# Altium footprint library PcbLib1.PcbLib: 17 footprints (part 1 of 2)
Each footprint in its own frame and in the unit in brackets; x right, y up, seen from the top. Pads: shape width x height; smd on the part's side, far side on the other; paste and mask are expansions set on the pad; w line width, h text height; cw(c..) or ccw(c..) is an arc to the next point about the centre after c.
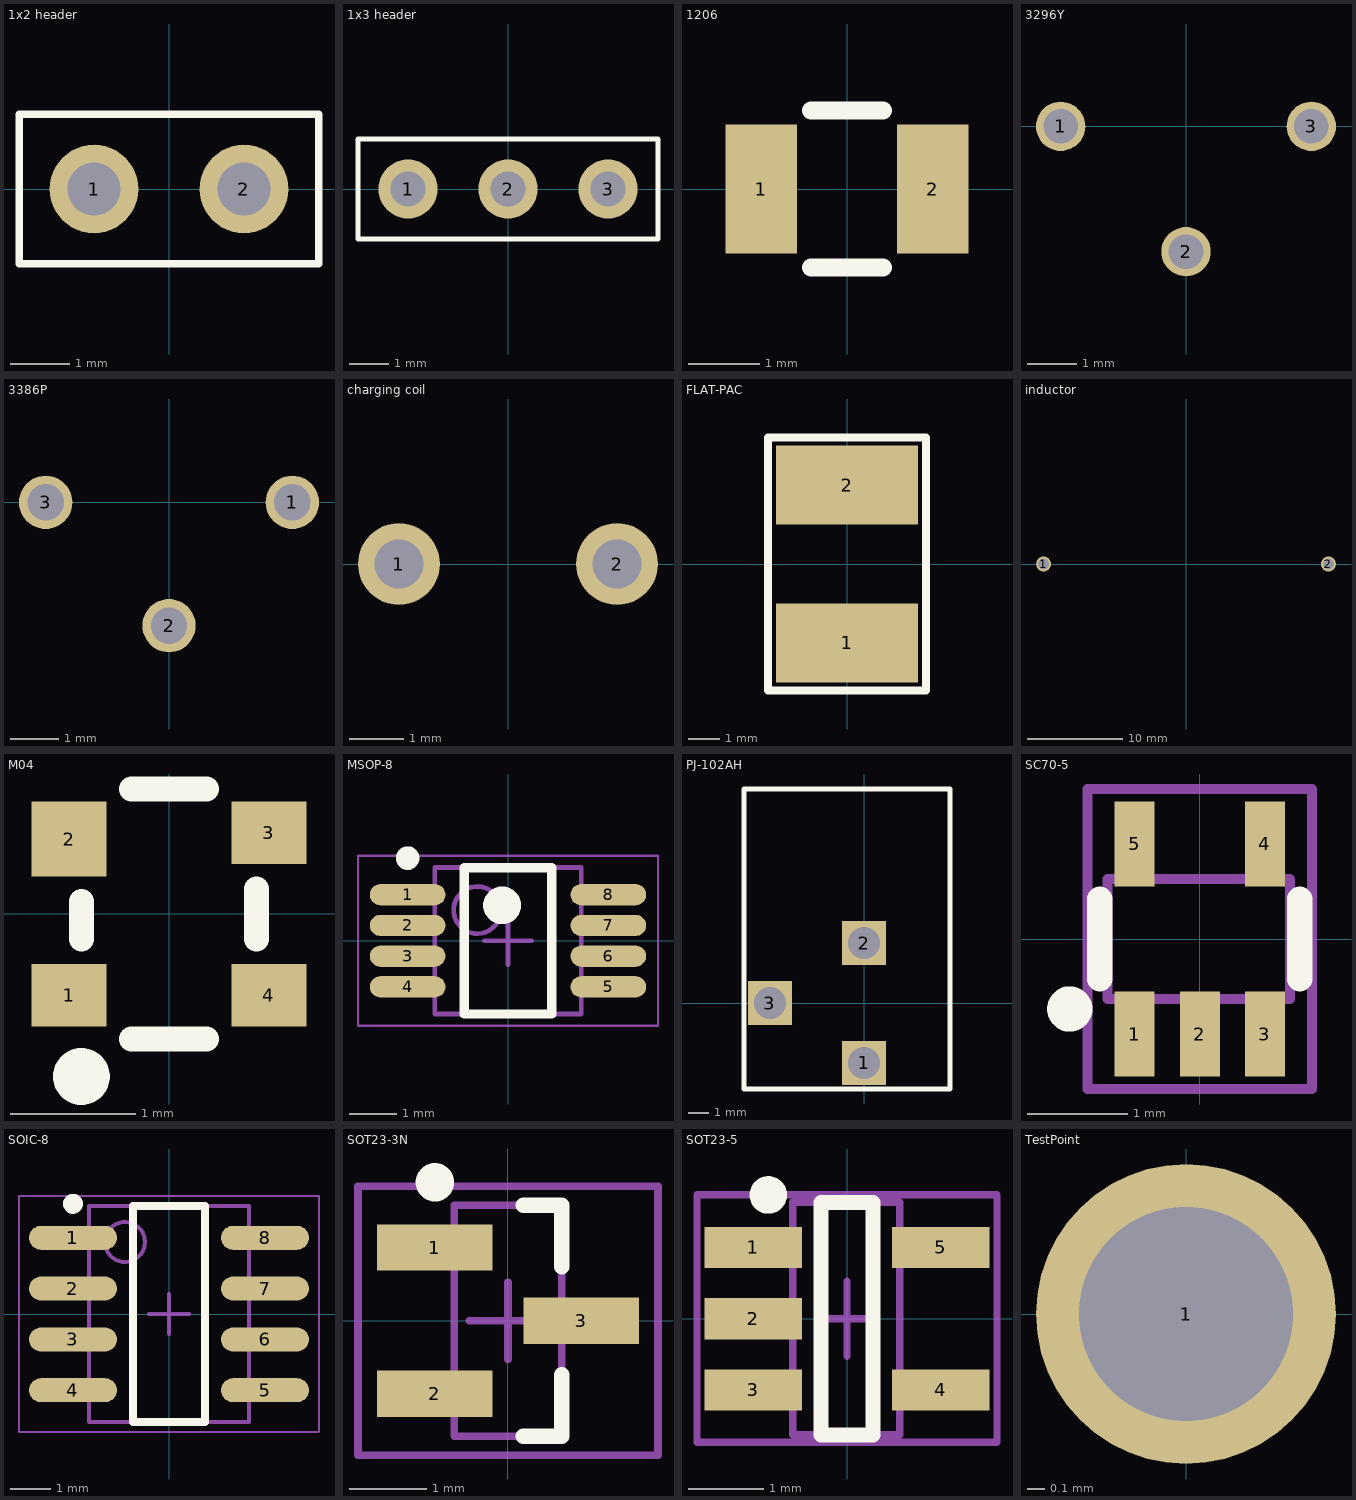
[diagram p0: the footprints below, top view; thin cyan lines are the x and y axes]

## 1x2 header [mm] "1x2 header, 100 mils"
pads (2):
  round 1.5 hole 0.9: 1(-1.27,0) 2(1.27,0)
Top Overlay:
  lines w0.127: -2.54,-1.27 -2.54,1.27 2.54,1.27 2.54,-1.27 -2.54,-1.27
3D body: height 2.54, standoff 0, extent -2.53,-1.26 2.53,1.26
3D body: height 8.38, standoff -1.52, extent -1.575,-0.305 -0.965,0.305
3D body: height 8.38, standoff -1.52, extent 0.965,-0.305 1.575,0.305

## 1x3 header [mm] "1x3 header, 100 mils"
pads (3):
  round 1.5 hole 0.9: 1(-2.54,0) 2(0,0) 3(2.54,0)
Top Overlay:
  lines w0.127: -3.81,-1.27 3.81,-1.27 3.81,1.27 -3.81,1.27 -3.81,-1.27
3D body: height 8.38, standoff -1.52, extent 2.235,-0.305 2.845,0.305
3D body: height 8.38, standoff -1.52, extent -0.305,-0.305 0.305,0.305
3D body: height 8.38, standoff -1.52, extent -2.845,-0.305 -2.235,0.305
3D body: height 2.54, standoff 0, extent -3.8,-1.25 3.8,1.25

## 1206 [mm]
pads (2):
  rect 1x1.8 smd: 1(-1.2,0) 2(1.2,0)
Top Overlay:
  lines w0.254: -0.5,-1.1 0.5,-1.1 ; -0.5,1.1 0.5,1.1
3D body: height 0.55, standoff 0, extent -1.6,-0.8 1.6,0.8

## 3296Y [mm] "Bourns 3296Y trimmer"
pads (3):
  round 1 hole 0.7: 1(-2.54,0) 2(0,-2.54) 3(2.54,0)
3D body: height 10, standoff 0, extent -4.8,-3.6 4.8,1.2
3D body: height 10.8, standoff 10, extent 2.209,-3.198 4.4,-1.002

## 3386P [mm] "trimming pot"
pads (3):
  round 1.1 hole 0.75: 1(2.54,0) 2(0,-2.54) 3(-2.54,0)
3D body: height 4.86, standoff 4.83, extent -2.5,-2.5 2.5,2.5
3D body: height 4.85, standoff 3.85, extent -2.877,-2.894 2.9,2.894
3D body: height 4.83, standoff 0, extent -4.8,-4.8 4.8,4.8

## charging coil [mm]
pads (2):
  round 1.5 hole 0.9: 1(-2,0) 2(2,0)

## FLAT-PAC [mm]
pads (2):
  rect 4.5x2.5 smd: 1(0,-2.5) 2(0,2.5)
Top Overlay:
  lines w0.254: -2.5,-4 2.5,-4 2.5,4 -2.5,4 -2.5,-4
3D body: height 1, standoff 0, extent -1.947,-3.494 1.947,3.494

## inductor [mm] "inductor 470mH"
pads (2):
  round 1.6 hole 1.15: 1(-15,0) 2(15,0)
3D body: height 15.44, standoff 0, extent -11.5,-7.735 11.5,7.735
3D body: height 8.16, standoff 7.34, extent 11.5,-0.409 15,0.409
3D body: height 8.16, standoff 7.34, extent -15,-0.409 -11.5,0.409
3D body: height 7.75, standoff -1.25, extent 14.593,-0.409 15.41,0.409
3D body: height 8.16, standoff 7.34, extent 14.594,-0.408 15.41,0.408
3D body: height 8.16, standoff 7.34, extent -15.406,-0.408 -14.59,0.408
3D body: height 7.75, standoff -1.25, extent -15.407,-0.409 -14.59,0.409

## M04 [mm] "FLAT-LEAD 4-PIN THIN-TYPE SUPER MINIMOLD (M04)"
pads (4):
  rect 0.6x0.5 smd: 1(-0.8,-0.65) 3(0.8,0.65) 4(0.8,-0.65)
  rect 0.6x0.6 smd: 2(-0.8,0.6)
Top Overlay:
  circle w0.254: c-0.7,-1.3 r0.1
  lines w0.2: -0.7,-0.2 -0.7,0.1 ; -0.3,-1 0.3,-1 ; -0.3,1 0.3,1 ; 0.7,-0.2 0.7,0.2
3D body: height 0.6, standoff 0, extent -0.7,-1 0.7,1

## MSOP-8 [mm] "TSOP, 8-Leads, Body 3.00x3.00mm, Pitch 0.65mm, IPC Medium Density"
height 1.1
pads (8):
  oval 1.6x0.45 smd: 1(-2.125,0.975) 2(-2.125,0.325) 3(-2.125,-0.325) 4(-2.125,-0.975) 5(2.125,-0.975) 6(2.125,-0.325) 7(2.125,0.325) 8(2.125,0.975)
Top Overlay:
  circle w0.25: c-2.125,1.75 r0.125
  circle w0.4: c-0.125,0.75 r0.2
  lines w0.2: -0.925,-1.55 -0.925,1.55 0.925,1.55 0.925,-1.55 -0.925,-1.55
Mechanical 13:
  circle w0.1: c-0.65,0.65 r0.5
  lines w0.1: -1.55,-1.55 -1.55,1.55 1.55,1.55 1.55,-1.55 -1.55,-1.55
Mechanical 15:
  lines w0.05: -3.175,-1.8 -3.175,1.8 3.175,1.8 3.175,-1.8 -3.175,-1.8
  lines w0.1: -0.5,0 0.5,0 ; 0,-0.5 0,0.5
3D body: height 1.1, standoff 0.1, extent -1.55,-1.55 1.55,1.55

## PJ-102AH [mm] "Power Jack"
pads (3):
  rect 2.2x2.2 hole 1.6: 1(0,-3) 2(0,3) 3(-4.7,0)
Top Overlay:
  lines w0.254: -6,-4.3 4.3,-4.3 4.3,10.7 -6,10.7 -6,0 -6,-4.3
3D body: height 10, standoff 0, extent -5.75,9.15 4.075,10.888
3D body: height 8.39, standoff 0.01, extent -4.975,-3.85 3.392,9.15
3D body: height 3, standoff 0, extent -5.75,-3.987 4.075,10.888

## SC70-5 [mm]
pads (5):
  rect 0.4x0.85 smd: 1(-0.65,-0.95) 2(0,-0.95) 3(0.65,-0.95) 4(0.65,0.95) 5(-0.65,0.95)
Top Overlay:
  circle w0.254: c-1.3,-0.7 r0.1
  lines w0.254: -1,-0.4 -1,0.4 ; 1,-0.4 1,0.4
Mechanical 12:
  text ".Designator" at -3.225,-0.15 h0.6
Mechanical 13:
  lines w0.1: -0.925,-0.6 -0.925,0.6 0.9,0.6 0.9,-0.6 -0.925,-0.6
Mechanical 15:
  lines w0.1: -1.125,-1.5 -1.125,1.5 1.125,1.5 1.125,-1.5 -1.125,-1.5
3D body: height 0.8, standoff 0, extent -0.9,-0.6 0.9,0.6

## SOIC-8 [mm] "SOIC, 8-Leads, Body 5.10x3.91mm, Pitch 1.27mm, IPC Medium Density"
height 1.75
pads (8):
  oval 2.2x0.6 smd: 1(-2.4,1.905) 2(-2.4,0.635) 3(-2.4,-0.635) 4(-2.4,-1.905) 5(2.4,-1.905) 6(2.4,-0.635) 7(2.4,0.635) 8(2.4,1.905)
Top Overlay:
  circle w0.25: c-2.4,2.755 r0.125
  lines w0.2: -0.9,-2.7 0.9,-2.7 0.9,2.7 -0.9,2.7 -0.9,-2.7
Mechanical 13:
  circle w0.1: c-1.1,1.8 r0.5
  lines w0.1: -2,-2.7 2,-2.7 2,2.7 -2,2.7 -2,-2.7
Mechanical 15:
  lines w0.05: -3.75,-2.95 3.75,-2.95 3.75,2.95 -3.75,2.95 -3.75,-2.95
  lines w0.1: -0.5,0 0.5,0 ; 0,-0.5 0,0.5
3D body: height 1.75, standoff 0.1, extent -2,-2.7 2,2.7

## SOT23-3N [mm] "SOT23, 3-Leads, Body 2.9x1.3mm, Pitch 0.95mm, Lead Span 2.5mm, IPC Medium Density"
height 1.1
pads (3):
  rect 1.5x0.6 smd: 1(-0.95,0.95) 2(-0.95,-0.95) 3(0.95,0)
Top Overlay:
  circle w0.25: c-0.95,1.8 r0.125
  lines w0.2: 0.2,-1.5 0.7,-1.5 0.7,-0.7 ; 0.2,1.5 0.7,1.5 0.7,0.7
Mechanical 13:
  lines w0.1: -0.7,-1.5 0.7,-1.5 0.7,1.5 -0.7,1.5 -0.7,-1.5
Mechanical 15:
  lines w0.1: -0.5,0 0.5,0 ; 0,-0.5 0,0.5 ; -1.95,-1.75 1.95,-1.75 1.95,1.75 -1.95,1.75 -1.95,-1.75
3D body: height 1.1, standoff 0, extent -0.7,-1.5 0.7,1.5

## SOT23-5 [mm] "SOT23, 5-Leads, Body 2.9x1.6mm, Pitch 0.95mm, Lead Span 2.8mm, IPC High Density"
height 1.45
pads (5):
  rect 1.3x0.55 smd: 1(-1.25,0.95) 2(-1.25,0) 3(-1.25,-0.95) 4(1.25,-0.95) 5(1.25,0.95)
Top Overlay:
  circle w0.25: c-1.05,1.65 r0.125
  lines w0.2: -0.35,-1.55 -0.35,1.55 0.35,1.55 0.35,-1.55 -0.35,-1.55
Mechanical 13:
  lines w0.1: -0.725,-1.55 0.7,-1.55 0.7,1.55 -0.725,1.55 -0.725,-1.55
Mechanical 15:
  lines w0.1: -0.375,0 0.35,0 ; 0,-0.5 0,0.5 ; -2,-1.65 2,-1.65 2,1.65 -2,1.65 -2,-1.65
3D body: height 1.45, standoff 0, extent -0.675,-1.5 0.65,1.5

## TestPoint [mm]
pads (1):
  round 1.68 hole 1.2: 1(0,0)
3D body: height 4.57, standoff 3.3, extent -0.628,-0.632 0.635,0.632
3D body: height 3.05, standoff 0, extent -1.26,-1.267 1.27,1.268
